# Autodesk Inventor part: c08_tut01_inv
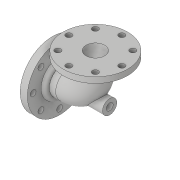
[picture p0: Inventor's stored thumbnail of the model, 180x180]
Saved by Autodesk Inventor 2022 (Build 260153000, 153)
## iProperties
Created: 2015-03
Part Number: c08_tut01_inv
Material: Generic
Document SubType Name: Modeling
Designer: Sandeep
Density: 1 g/cm^3
Appearance: Default
Author: Sandeep
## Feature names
1. Sweep1
2. Shell1
3. Extrusion1
4. Extrusion2
5. Extrusion3
6. Extrusion4
7. Fillet1
8. Extrusion5
9. Circular Pattern1
10. Extrusion6
11. Circular Pattern2
12. Extrusion7
13. Hole1
## Parameters: d1 = 35 mm, d2 = 35 mm, d4 = 97 mm, d5 = 0, d6 = 0, d7 = 16 mm, d8 = 225 mm, d10 = 0, d11 = 225 mm, d13 = 25 mm, d14 = 0, d15 = 86 mm, d16 = 22 mm, d17 = 0, d18 = 129 mm, d19 = 16 mm, d20 = 0, d21 = 16 mm, d22 = 185 mm, d23 = 20.5 mm, d24 = 0, d25 = 0, d27 = 360 deg, d29 = 185 mm, d30 = 20.5 mm, d31 = 16 mm, d32 = 0, d34 = 360 deg, d37 = 175 mm, d39 = 145 mm, d40 = 16 mm, d41 = 0, d45 = 6 mm, d46 = 24 mm, d47 = 28 mm, d48 = 90 deg, d49 = 8 mm, d50 = 118 deg
